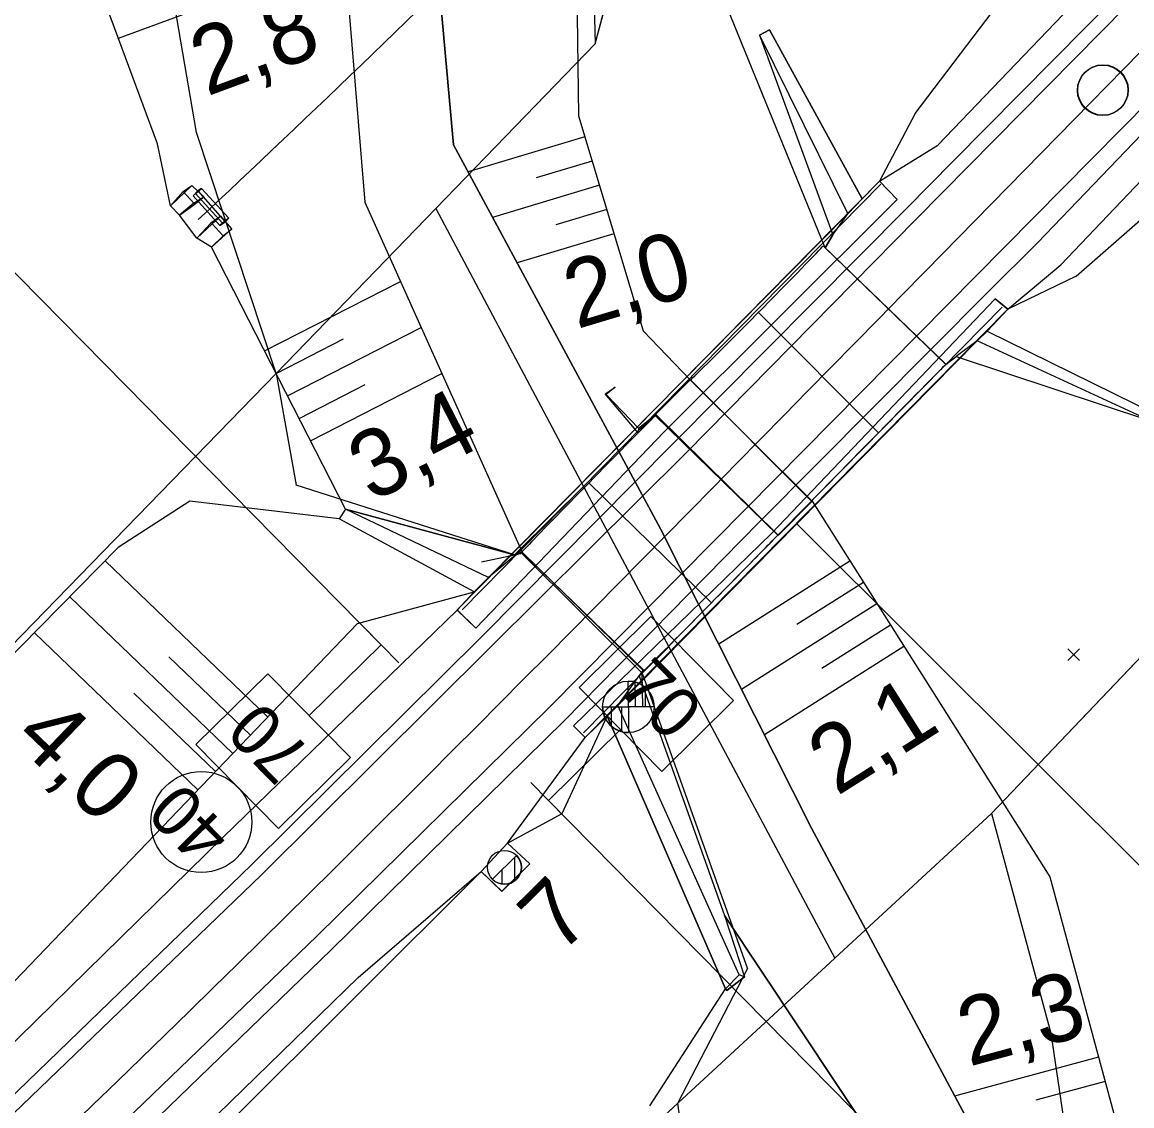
# Model space of a CAD drawing. Extents: x -800194 to -799078, y -1007177 to -1006597.
# Drawn here: x -799442.55 to -799409.59, y -1006906.91 to -1006874.74 of the extents above; entities that cross this region are included whole.
import ezdxf

# ---------------------------------------------------------------- set-up
doc = ezdxf.new("R2010")
doc.units = 0
for name, color, linetype in [('02_Osa_koleje', 7, 'Continuous'), ('_návrh', 7, 'Continuous'), ('Vrstva 1', 7, 'Continuous'), ('Vrstva 11', 7, 'Continuous'), ('Vrstva 12', 7, 'Continuous'), ('Vrstva 17', 7, 'Continuous'), ('Vrstva 18', 7, 'Continuous'), ('Vrstva 23', 7, 'Continuous'), ('Vrstva 4', 7, 'Continuous'), ('Vrstva 47', 7, 'Continuous'), ('Vrstva 48', 7, 'Continuous'), ('Vrstva 49', 7, 'Continuous'), ('Vrstva 5', 7, 'Continuous'), ('Vrstva 50', 7, 'Continuous'), ('Vrstva 53', 7, 'Continuous'), ('Vrstva 55', 7, 'Continuous'), ('Vrstva 56', 7, 'Continuous'), ('Vrstva 63', 7, 'Continuous'), ('Vrstva 7', 7, 'Continuous')]:
    doc.layers.add(name, color=color, linetype=linetype)

msp = doc.modelspace()

# ---------------------------------------------------------------- linework, layer by layer
at = {"layer": '02_Osa_koleje'}
msp.add_lwpolyline([(-799415.714, -1006882.127), (-799416.414, -1006882.841), (-799417.114, -1006883.555), (-799417.815, -1006884.269), (-799418.515, -1006884.983), (-799419.215, -1006885.696), (-799419.916, -1006886.41), (-799420.617, -1006887.123), (-799421.318, -1006887.836), (-799422.019, -1006888.549), (-799422.721, -1006889.262), (-799423.423, -1006889.974), (-799424.125, -1006890.686), (-799424.828, -1006891.398), (-799425.531, -1006892.109), (-799426.234, -1006892.819), (-799426.938, -1006893.529), (-799427.643, -1006894.239), (-799428.348, -1006894.948), (-799429.054, -1006895.657), (-799429.76, -1006896.365), (-799430.467, -1006897.072), (-799431.174, -1006897.779), (-799431.883, -1006898.484), (-799432.592, -1006899.19), (-799433.302, -1006899.894), (-799434.012, -1006900.598), (-799434.724, -1006901.3), (-799435.436, -1006902.002), (-799436.149, -1006902.703), (-799436.864, -1006903.403), (-799437.579, -1006904.102), (-799438.295, -1006904.8), (-799439.012, -1006905.497), (-799439.73, -1006906.193), (-799440.449, -1006906.887), (-799441.17, -1006907.581)], dxfattribs=at)
at = {"layer": '_návrh'}
msp.add_line((-799415.714, -1006882.127), (-799404.558, -1006870.75), dxfattribs=at)
at = {"layer": 'Vrstva 1'}
msp.add_line((-799415.714, -1006882.127), (-799297.339, -1006761.401), dxfattribs=at)
at = {"layer": 'Vrstva 11'}
for p, q in [((-799427.864, -1006899.477), (-799428.58, -1006900.183)), ((-799427.917, -1006900.229), (-799427.913, -1006899.525)), ((-799428.293, -1006900.324), (-799428.29, -1006899.897))]:
    msp.add_line(p, q, dxfattribs=at)
msp.add_circle((-799428.222, -1006899.83), 0.503, dxfattribs=at)
msp.add_arc((-799428.222, -1006899.83), 0.503, 224.5927, 44.5927, dxfattribs=at)
at = {"layer": 'Vrstva 12'}
for p, q in [((-799437.769, -1006879.761), (-799437.512, -1006879.586)), ((-799437.452, -1006880.113), (-799437.147, -1006879.929)), ((-799436.644, -1006880.497), (-799436.908, -1006880.728)), ((-799436.578, -1006881.084), (-799436.322, -1006880.878)), ((-799425.197, -1006885.793), (-799425.235, -1006885.77)), ((-799424.241, -1006886.797), (-799424.247, -1006886.93)), ((-799427.466, -1006899.73), (-799427.466, -1006899.73)), ((-799428.298, -1006900.543), (-799428.299, -1006900.544))]:
    msp.add_line(p, q, dxfattribs=at)
for points in [[(-799437.876, -1006880.464), (-799437.451, -1006880.166), (-799437.147, -1006879.929), (-799437.512, -1006879.586), (-799438.146, -1006880.193)], [(-799437.876, -1006880.464), (-799438.146, -1006880.193), (-799437.769, -1006879.761), (-799437.452, -1006880.113), (-799437.876, -1006880.464)], [(-799436.923, -1006881.42), (-799436.322, -1006880.878), (-799436.644, -1006880.497), (-799436.942, -1006880.704), (-799437.363, -1006881.152)], [(-799437.363, -1006881.152), (-799436.908, -1006880.728), (-799436.578, -1006881.084), (-799436.923, -1006881.42), (-799437.363, -1006881.152)], [(-799423.751, -1006886.402), (-799424.247, -1006886.93), (-799425.235, -1006885.77), (-799424.934, -1006885.579)], [(-799424.934, -1006885.579), (-799425.197, -1006885.793), (-799424.241, -1006886.797), (-799423.751, -1006886.402)], [(-799428.918, -1006899.95), (-799428.299, -1006900.544), (-799427.466, -1006899.73), (-799428.131, -1006899.117)], [(-799428.918, -1006899.95), (-799428.298, -1006900.543), (-799427.466, -1006899.73), (-799428.131, -1006899.117), (-799428.918, -1006899.95)]]:
    msp.add_lwpolyline(points, dxfattribs=at)
at = {"layer": 'Vrstva 17'}
for p, q in [((-799429.476, -1006892.183), (-799417.039, -1006879.551)), ((-799413.44, -1006883.204), (-799425.878, -1006895.835))]:
    msp.add_line(p, q, dxfattribs=at)
at = {"layer": 'Vrstva 18'}
for p, q in [((-799420.643, -1006875.124), (-799418.02, -1006880.424)), ((-799418.753, -1006881.374), (-799415.11, -1006884.892)), ((-799418.695, -1006881.438), (-799415.112, -1006884.906)), ((-799413.268, -1006883.26), (-799425.823, -1006895.98)), ((-799420.678, -1006883.354), (-799417.113, -1006886.928)), ((-799422.705, -1006885.358), (-799419.086, -1006888.964)), ((-799422.697, -1006885.359), (-799419.103, -1006888.958)), ((-799423.751, -1006886.402), (-799420.096, -1006889.979)), ((-799423.712, -1006886.397), (-799420.097, -1006889.96)), ((-799425.715, -1006888.42), (-799422.073, -1006891.977)), ((-799429.125, -1006891.656), (-799433.133, -1006889.484)), ((-799380.318, -1006928.766), (-799419.546, -1006889.62)), ((-799427.701, -1006890.47), (-799424.076, -1006893.99)), ((-799424.101, -1006893.992), (-799427.694, -1006890.471))]:
    msp.add_line(p, q, dxfattribs=at)
for points in [[(-799420.643, -1006875.124), (-799420.353, -1006874.964), (-799417.6, -1006879.987)], [(-799420.643, -1006875.124), (-799418.471, -1006881.053), (-799418.02, -1006880.424)], [(-799429.627, -1006892.19), (-799429.629, -1006892.192), (-799429.125, -1006891.656), (-799428.698, -1006891.23), (-799418.02, -1006880.424), (-799417.6, -1006879.987), (-799417.085, -1006879.46), (-799417.085, -1006879.46)], [(-799429.07, -1006892.727), (-799423.479, -1006886.901), (-799416.56, -1006880.007), (-799417.085, -1006879.46), (-799429.627, -1006892.19), (-799429.07, -1006892.727)], [(-799416.56, -1006880.007), (-799417.085, -1006879.46)], [(-799418.753, -1006881.374), (-799418.695, -1006881.438), (-799418.471, -1006881.053)], [(-799425.824, -1006895.981), (-799425.823, -1006895.98), (-799426.173, -1006895.627), (-799425.824, -1006895.981), (-799425.17, -1006895.342), (-799424.851, -1006895.023), (-799414.182, -1006884.2), (-799413.881, -1006883.908), (-799413.271, -1006883.261), (-799413.268, -1006883.26), (-799413.647, -1006882.957), (-799413.271, -1006883.261)], [(-799426.173, -1006895.627), (-799420.283, -1006889.914), (-799413.647, -1006882.957)], [(-799413.881, -1006883.908), (-799408.874, -1006886.377), (-799409.032, -1006886.579)], [(-799414.182, -1006884.2), (-799414.808, -1006884.66), (-799409.032, -1006886.579), (-799414.182, -1006884.2)], [(-799415.11, -1006884.892), (-799415.112, -1006884.906), (-799414.808, -1006884.66)], [(-799423.712, -1006886.397), (-799423.751, -1006886.402), (-799422.705, -1006885.358), (-799422.697, -1006885.359)], [(-799420.097, -1006889.96), (-799420.096, -1006889.979), (-799419.086, -1006888.964), (-799419.103, -1006888.958)], [(-799428.698, -1006891.23), (-799432.944, -1006889.197), (-799433.133, -1006889.484)], [(-799432.944, -1006889.197), (-799427.892, -1006890.566), (-799428.698, -1006891.23)], [(-799427.892, -1006890.566), (-799427.694, -1006890.471), (-799427.701, -1006890.47)], [(-799429.07, -1006892.727), (-799429.629, -1006892.192)], [(-799424.223, -1006894.144), (-799424.101, -1006893.992), (-799424.076, -1006893.99)], [(-799421.25, -1006903.021), (-799424.851, -1006895.023), (-799424.223, -1006894.144), (-799421.688, -1006901.262), (-799421.096, -1006903.085)], [(-799425.17, -1006895.342), (-799421.655, -1006903.434), (-799421.617, -1006903.488), (-799421.096, -1006903.085), (-799421.25, -1006903.021), (-799421.655, -1006903.434)]]:
    msp.add_lwpolyline(points, dxfattribs=at)
for centre, major_axis, ratio, start_param, end_param in [((-799420.724, -1006883.362), (-1.983, -2.004), 0.009761, 0.092672, 3.023238), ((-799417.106, -1006886.925), (-1.997, -2.033), 0.000898, 3.15336, 6.275981), ((-799425.738, -1006888.463), (-2.026, -2.066), 0.004773, 3.137657, 6.529051), ((-799422.096, -1006891.985), (-1.999, -2.025), 0.003643, 6.144403, 9.411645)]:
    msp.add_ellipse(centre, major_axis=major_axis, ratio=ratio, start_param=start_param, end_param=end_param, dxfattribs=at)
at = {"layer": 'Vrstva 23'}
for p, q in [((-799437.399, -1006879.826), (-799436.594, -1006880.708)), ((-799437.328, -1006879.75), (-799436.517, -1006880.669)), ((-799437.219, -1006879.681), (-799436.41, -1006880.559)), ((-799436.679, -1006880.778), (-799437.467, -1006879.896))]:
    msp.add_line(p, q, dxfattribs=at)
for points in [[(-799437.467, -1006879.896), (-799437.399, -1006879.826), (-799437.219, -1006879.681), (-799437.328, -1006879.75), (-799437.467, -1006879.896)], [(-799436.517, -1006880.669), (-799436.41, -1006880.559), (-799436.594, -1006880.708), (-799436.679, -1006880.778), (-799436.517, -1006880.669)]]:
    msp.add_lwpolyline(points, dxfattribs=at)
at = {"layer": 'Vrstva 4'}
for points in [[(-799415.349, -1006878.386), (-799401.641, -1006864.104), (-799387.486, -1006849.959), (-799372.535, -1006834.618), (-799359.471, -1006821.017), (-799348.425, -1006810.321), (-799332.246, -1006792.656), (-799316.193, -1006777.023)], [(-799414.896, -1006878.87), (-799401.02, -1006864.85), (-799386.827, -1006850.567), (-799372.152, -1006835.069), (-799358.827, -1006821.464), (-799347.624, -1006811), (-799330.977, -1006793.164), (-799315.559, -1006777.544)], [(-799412.388, -1006881.287), (-799398.609, -1006866.93), (-799384.751, -1006852.862), (-799369.474, -1006837.434), (-799356.035, -1006824.081), (-799345.419, -1006813.083), (-799328.801, -1006795.774), (-799312.796, -1006779.76)], [(-799411.693, -1006881.939), (-799397.907, -1006867.466), (-799384.258, -1006853.369), (-799368.884, -1006838.066), (-799355.624, -1006824.532), (-799352.562, -1006821.889), (-799351.649, -1006821.039), (-799351.009, -1006819.785)], [(-799510.394, -1006958.536), (-799498.027, -1006951.328), (-799477.988, -1006937.435), (-799460.33, -1006923.117), (-799451.862, -1006915.581), (-799443.604, -1006907.9), (-799435.444, -1006900.067), (-799428.64, -1006893.299), (-799422.817, -1006887.511), (-799415.998, -1006880.595), (-799408.158, -1006872.652), (-799401.02, -1006864.85)], [(-799509.248, -1006960.724), (-799497.456, -1006953.809), (-799476.495, -1006939.437), (-799458.707, -1006924.982), (-799450.277, -1006917.43), (-799441.932, -1006909.717), (-799433.783, -1006901.867), (-799426.9, -1006895.092), (-799421.037, -1006889.182), (-799414.218, -1006882.281), (-799406.443, -1006874.417), (-799398.609, -1006866.93)], [(-799511.236, -1006957.129), (-799499.236, -1006950.771), (-799498.598, -1006949.914), (-799498.679, -1006949.705), (-799496.151, -1006948.479), (-799496.251, -1006948.258), (-799490.687, -1006944.683), (-799490.497, -1006944.878), (-799488.249, -1006943.052), (-799488.105, -1006943.216), (-799486.269, -1006941.68), (-799478.997, -1006936.484), (-799474.568, -1006932.916), (-799474.237, -1006932.694), (-799461.519, -1006921.99), (-799452.935, -1006914.372), (-799444.695, -1006906.886), (-799436.579, -1006898.932), (-799429.629, -1006892.192), (-799429.07, -1006892.727), (-799423.479, -1006886.901), (-799416.56, -1006880.007), (-799417.085, -1006879.46), (-799415.349, -1006878.386)], [(-799510.726, -1006958.045), (-799497.901, -1006950.516), (-799478.36, -1006937.055), (-799461.534, -1006923.53), (-799452.128, -1006915.305), (-799443.894, -1006907.632), (-799435.739, -1006899.754), (-799428.922, -1006893.007), (-799423.223, -1006887.256), (-799416.277, -1006880.269), (-799414.896, -1006878.87)], [(-799509.087, -1006961.127), (-799497.277, -1006954.118), (-799476.183, -1006939.802), (-799458.586, -1006925.284), (-799449.914, -1006917.869), (-799441.499, -1006910.139), (-799433.371, -1006902.28), (-799426.451, -1006895.478), (-799420.657, -1006889.585), (-799413.85, -1006882.742), (-799412.388, -1006881.287)], [(-799475.489, -1006940.774), (-799457.684, -1006926.366), (-799456.318, -1006925.174), (-799455.328, -1006924.513), (-799448.961, -1006918.843), (-799440.534, -1006910.864), (-799432.566, -1006903.097), (-799428.918, -1006899.95), (-799428.131, -1006899.117), (-799425.824, -1006895.981), (-799426.173, -1006895.627), (-799420.283, -1006889.914), (-799413.647, -1006882.957), (-799413.271, -1006883.261), (-799411.693, -1006881.939)]]:
    msp.add_lwpolyline(points, dxfattribs=at)
at = {"layer": 'Vrstva 47'}
msp.add_ellipse((-799432.733, -1006875.845), major_axis=(8.482, 8.158), ratio=0.02521, start_param=4.117511, end_param=5.400082, dxfattribs=at)
at = {"layer": 'Vrstva 48'}
for p, q in [((-799439.685, -1006875.218), (-799432.976, -1006872.737)), ((-799425.83, -1006878.145), (-799429.299, -1006879.185)), ((-799425.615, -1006878.863), (-799427.275, -1006879.361)), ((-799425.399, -1006879.581), (-799428.572, -1006880.533)), ((-799425.184, -1006880.3), (-799426.696, -1006880.753)), ((-799424.968, -1006881.018), (-799427.844, -1006881.881)), ((-799435.348, -1006884.498), (-799431.312, -1006882.433)), ((-799434.665, -1006885.834), (-799430.695, -1006883.803)), ((-799435.006, -1006885.166), (-799433.005, -1006884.142)), ((-799433.981, -1006887.169), (-799430.079, -1006885.173)), ((-799434.323, -1006886.502), (-799432.355, -1006885.495)), ((-799435.25, -1006895.368), (-799440.081, -1006890.727)), ((-799417.962, -1006890.738), (-799421.856, -1006893.206)), ((-799417.561, -1006891.372), (-799419.539, -1006892.625)), ((-799436.29, -1006896.449), (-799441.134, -1006891.796)), ((-799417.159, -1006892.005), (-799421.178, -1006894.552)), ((-799416.758, -1006892.639), (-799418.799, -1006893.932)), ((-799437.329, -1006897.531), (-799442.186, -1006892.865)), ((-799416.356, -1006893.272), (-799420.501, -1006895.898)), ((-799435.77, -1006895.908), (-799438.189, -1006893.585)), ((-799436.809, -1006896.99), (-799439.234, -1006894.66)), ((-799410.574, -1006905.468), (-799414.85, -1006906.623)), ((-799410.379, -1006906.192), (-799412.433, -1006906.747))]:
    msp.add_line(p, q, dxfattribs=at)
at = {"layer": 'Vrstva 49'}
for p, q in [((-799417.6, -1006879.987), (-799420.353, -1006874.964)), ((-799411.491, -1006893.34), (-799411.137, -1006893.694)), ((-799411.491, -1006893.694), (-799411.137, -1006893.34))]:
    msp.add_line(p, q, dxfattribs=at)
for points in [[(-799416.02, -1006877.454), (-799404.211, -1006861.901), (-799389.752, -1006848.65), (-799373.943, -1006833.474), (-799360.851, -1006819.663), (-799350.223, -1006808.887), (-799332.885, -1006792.133), (-799317.349, -1006776.174)], [(-799411.244, -1006882.282), (-799396.463, -1006869.344), (-799382.442, -1006854.946), (-799367.277, -1006839.246), (-799355.518, -1006825.988), (-799351.844, -1006822.661), (-799350.97, -1006821.769), (-799343.258, -1006815.248), (-799325.688, -1006798.253), (-799311.274, -1006781.732)], [(-799410.227, -1006925.149), (-799412.491, -1006911.033), (-799419.106, -1006898.668), (-799423.582, -1006889.778), (-799429.735, -1006878.378), (-799431.818, -1006855.328)], [(-799426.038, -1006858.234), (-799426.419, -1006863.568), (-799427.212, -1006869.673), (-799426.968, -1006870.003), (-799426.4, -1006870.552), (-799426.115, -1006870.824), (-799426.018, -1006877.519), (-799424.103, -1006883.903), (-799422.705, -1006885.358), (-799423.751, -1006886.402), (-799420.096, -1006889.979), (-799419.086, -1006888.964), (-799412.022, -1006900.113), (-799405.487, -1006924.286)], [(-799427.694, -1006890.471), (-799427.892, -1006890.566), (-799432.944, -1006889.197), (-799436.923, -1006881.42), (-799437.363, -1006881.152), (-799437.876, -1006880.464), (-799438.146, -1006880.193), (-799438.528, -1006878.348), (-799441.503, -1006870.303), (-799439.353, -1006865.427), (-799439.436, -1006859.851)], [(-799433.824, -1006862.471), (-799432.369, -1006880.085), (-799427.694, -1006890.471)], [(-799418.695, -1006881.438), (-799422.419, -1006872.299), (-799420.397, -1006870.813)], [(-799420.353, -1006874.964), (-799420.643, -1006875.124), (-799418.471, -1006881.053), (-799418.695, -1006881.438)], [(-799416.02, -1006877.454), (-799417.085, -1006879.46), (-799417.6, -1006879.987)], [(-799411.244, -1006882.282), (-799413.271, -1006883.261), (-799413.881, -1006883.908)], [(-799413.881, -1006883.908), (-799408.874, -1006886.377), (-799409.032, -1006886.579), (-799405.305, -1006888.801)], [(-799429.125, -1006891.656), (-799433.133, -1006889.484), (-799437.572, -1006888.963), (-799439.693, -1006890.332), (-799461.15, -1006912.135), (-799487.142, -1006929.222), (-799487.006, -1006931.546), (-799490.308, -1006935.771)], [(-799490.09, -1006944.145), (-799488.194, -1006942.597), (-799488.011, -1006942.815), (-799488.011, -1006942.815), (-799486.419, -1006941.508), (-799486.269, -1006941.68), (-799484.618, -1006939.109), (-799474.926, -1006932.405), (-799474.596, -1006932.171), (-799461.519, -1006921.99), (-799452.935, -1006914.372), (-799445.566, -1006906.106), (-799432.588, -1006892.596), (-799429.125, -1006891.656)], [(-799486.865, -1006949.018), (-799484.86, -1006947.727), (-799485.016, -1006947.459), (-799485.713, -1006947.881), (-799483.734, -1006946.536), (-799483.686, -1006946.569), (-799483.396, -1006947.063), (-799482.389, -1006946.51), (-799482.647, -1006946.068), (-799475.489, -1006940.774), (-799464.892, -1006933.871), (-799456.989, -1006927.138), (-799455.117, -1006925.642), (-799440.165, -1006911.165), (-799428.918, -1006899.95), (-799428.299, -1006900.544), (-799427.466, -1006899.73), (-799428.131, -1006899.117), (-799426.509, -1006898.237), (-799425.17, -1006895.342)], [(-799421.655, -1006903.434), (-799425.17, -1006895.342)], [(-799413.387, -1006925.296), (-799414.969, -1006911.36), (-799421.688, -1006901.262)], [(-799421.688, -1006901.262), (-799421.096, -1006903.085), (-799421.617, -1006903.488), (-799421.655, -1006903.434)], [(-799423.903, -1006906.911), (-799421.655, -1006903.434)]]:
    msp.add_lwpolyline(points, dxfattribs=at)
at = {"layer": 'Vrstva 5'}
for p, q in [((-799466.989, -1006857.616), (-799431.886, -1006893.222)), ((-799431.359, -1006893.756), (-799432.413, -1006892.688)), ((-799431.886, -1006893.222), (-799434.022, -1006895.328)), ((-799426.915, -1006897.844), (-799424.779, -1006895.738)), ((-799427.442, -1006897.31), (-799426.388, -1006898.378)), ((-799389.844, -1006935.446), (-799426.915, -1006897.844))]:
    msp.add_line(p, q, dxfattribs=at)
for points in [[(-799423.55, -1006896.984), (-799426.007, -1006894.492), (-799423.871, -1006892.385), (-799421.414, -1006894.878)], [(-799435.251, -1006894.082), (-799432.794, -1006896.574), (-799434.93, -1006898.681), (-799437.387, -1006896.188)]]:
    msp.add_lwpolyline(points, close=True, dxfattribs=at)
msp.add_circle((-799437.227, -1006898.487), 1.5, dxfattribs=at)
at = {"layer": 'Vrstva 50'}
for points in [[(-799431.818, -1006855.328), (-799429.735, -1006878.378), (-799423.582, -1006889.778), (-799419.106, -1006898.668), (-799412.491, -1006911.033), (-799410.227, -1006925.149)], [(-799433.824, -1006862.471), (-799432.369, -1006880.085), (-799427.694, -1006890.471), (-799424.101, -1006893.992), (-799424.223, -1006894.144), (-799421.688, -1006901.262), (-799414.969, -1006911.36), (-799413.387, -1006925.296)]]:
    msp.add_lwpolyline(points, dxfattribs=at)
at = {"layer": 'Vrstva 53'}
for points in [[(-799559.64, -1006968.48), (-799519.68, -1006952.01), (-799500.87, -1006940.41), (-799496.64, -1006937.8), (-799494.85, -1006936.7), (-799484.519, -1006930.319), (-799457.99, -1006908.8), (-799435, -1006885.17), (-799430.26, -1006880.27), (-799425.53, -1006875.38), (-799422.55, -1006864.36), (-799390.88, -1006834), (-799358.35, -1006806.65), (-799352.29, -1006801.56), (-799330.91, -1006783.58), (-799314.235, -1006766.649)], [(-799312.398, -1006791.976), (-799331.37, -1006811.87), (-799413.75, -1006898.23), (-799418.41, -1006902.53), (-799423.07, -1006906.83), (-799433.4, -1006916.39), (-799469.5, -1006946.86), (-799487.22, -1006958.47), (-799495.25, -1006963.74), (-799521.98, -1006977.8), (-799546.71, -1006987.83)]]:
    msp.add_lwpolyline(points, dxfattribs=at)
at = {"layer": 'Vrstva 55'}
for p, q in [((-799413.75, -1006898.23), (-799331.37, -1006811.87)), ((-799425.53, -1006875.38), (-799422.55, -1006864.36)), ((-799425.53, -1006875.38), (-799430.26, -1006880.27)), ((-799430.26, -1006880.27), (-799435, -1006885.17)), ((-799430.26, -1006880.27), (-799425.87, -1006888.52)), ((-799425.87, -1006888.52), (-799423.34, -1006893.28)), ((-799423.34, -1006893.28), (-799418.41, -1006902.53)), ((-799418.41, -1006902.53), (-799413.75, -1006898.23)), ((-799423.07, -1006906.83), (-799418.41, -1006902.53)), ((-799433.4, -1006916.39), (-799423.07, -1006906.83))]:
    msp.add_line(p, q, dxfattribs=at)
for points in [[(-799422.547, -1006766.649), (-799420.88, -1006776.85), (-799422, -1006788.79), (-799422.77, -1006803.25), (-799426.4, -1006820.84), (-799428.26, -1006838.83), (-799427.88, -1006846.03), (-799426.08, -1006854.14), (-799425.53, -1006875.38)], [(-799435, -1006885.17), (-799437.37, -1006878.01), (-799439.06, -1006868.14)], [(-799494.85, -1006936.7), (-799484.52, -1006930.32), (-799457.99, -1006908.8), (-799435, -1006885.17)], [(-799413.75, -1006898.23), (-799411.99, -1006904.75), (-799406.72, -1006940.36), (-799397.01, -1006988.73)], [(-799410.89, -1007000.14), (-799412.5, -1006983.38), (-799423.07, -1006906.83)]]:
    msp.add_lwpolyline(points, dxfattribs=at)
at = {"layer": 'Vrstva 56'}
for p, q in [((-799435, -1006885.17), (-799434.41, -1006888.48)), ((-799427.92, -1006890.55), (-799434.41, -1006888.48)), ((-799427.79, -1006890.42), (-799425.87, -1006888.52)), ((-799428.899, -1006890.757), (-799427.921, -1006890.55)), ((-799427.92, -1006890.55), (-799427.79, -1006890.42)), ((-799427.79, -1006890.42), (-799425.84, -1006892.36)), ((-799425.84, -1006892.36), (-799424.13, -1006894.07)), ((-799423.34, -1006893.28), (-799424.13, -1006894.07)), ((-799424.113, -1006895.07), (-799424.131, -1006894.071)), ((-799424.13, -1006894.07), (-799421, -1006902.84)), ((-799423.07, -1006906.83), (-799421, -1006902.84))]:
    msp.add_line(p, q, dxfattribs=at)
at = {"layer": 'Vrstva 63'}
for p, q in [((-799424.541, -1006895.067), (-799424.542, -1006894.303)), ((-799424.333, -1006895.067), (-799424.334, -1006894.331)), ((-799424.033, -1006895.067), (-799424.033, -1006894.496)), ((-799425.305, -1006895.062), (-799424.541, -1006895.067)), ((-799425.037, -1006895.649), (-799425.037, -1006895.064)), ((-799424.737, -1006895.806), (-799424.737, -1006895.066)), ((-799423.776, -1006895.066), (-799424.541, -1006895.067)), ((-799424.541, -1006895.067), (-799424.54, -1006895.832))]:
    msp.add_line(p, q, dxfattribs=at)
msp.add_circle((-799424.541, -1006895.067), 0.764, dxfattribs=at)
for centre, start, end in [((-799424.542, -1006895.068), 0.1128, 90.0063), ((-799424.54, -1006895.066), 179.662, 269.98)]:
    msp.add_arc(centre, 0.765, start, end, dxfattribs=at)
at = {"layer": 'Vrstva 7'}
for centre in [(-799410.454, -1006876.763), (-799410.443, -1006876.752)]:
    msp.add_circle(centre, 0.75, dxfattribs=at)

# ---------------------------------------------------------------- texts
at = {"layer": 'Vrstva 11'}
msp.add_text('7', height=2, rotation=44.5927, dxfattribs=at).set_placement((-799426.568, -1006902.454))
at = {"layer": 'Vrstva 48'}
for s, rotation, p in [('2,8', 20.2941, (-799437.062, -1006876.949)), ('2,0', 16.6976, (-799426.075, -1006883.857)), ('3,4', 27.096, (-799432.164, -1006889.01)), ('2,1', 32.3583, (-799418.346, -1006897.73)), ('4,0', 316.1506, (-799442.863, -1006896.053)), ('2,3', 15.1279, (-799414.428, -1006905.752))]:
    msp.add_text(s, height=2, rotation=rotation, dxfattribs=at).set_placement(p)
at = {"layer": 'Vrstva 5'}
for s, rotation, p in [('70', 314.5927, (-799424.886, -1006894.561)), ('70', 134.5927, (-799433.907, -1006896.414)), ('40', 134.5927, (-799436.265, -1006898.822))]:
    msp.add_text(s, height=1.5, rotation=rotation, dxfattribs=at).set_placement(p)

doc.saveas('drawing.dxf')
